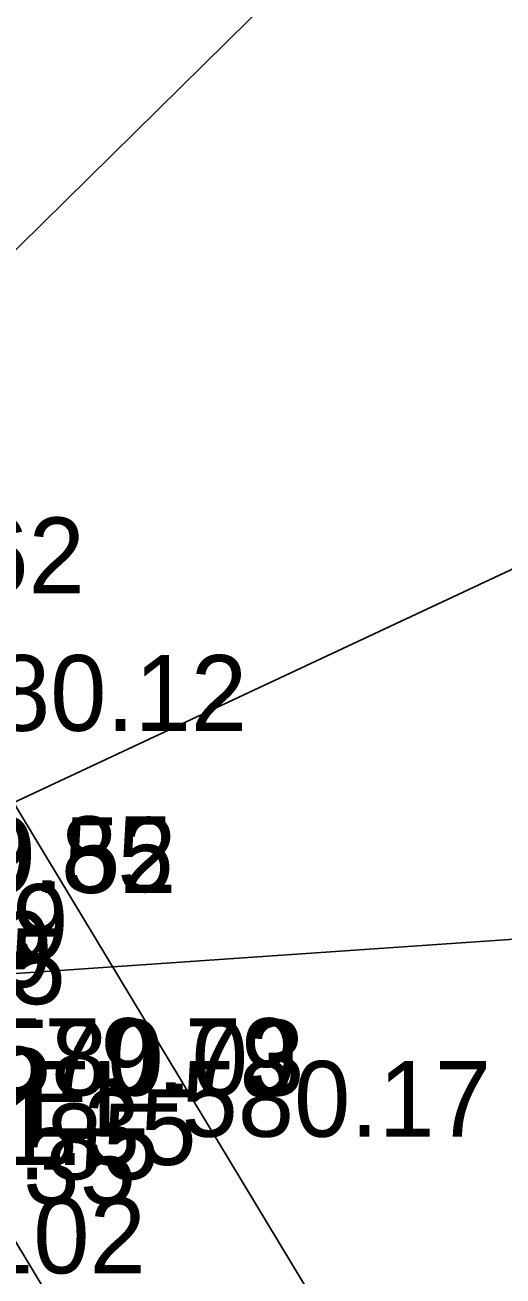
# Model space of a CAD drawing. Extents: x 1729869 to 1735532, y 648588 to 653771.
# Drawn here: x 1731709 to 1731734.2, y 651454.2 to 651520.3 of the extents above; entities that cross this region are included whole.
import ezdxf

# ---------------------------------------------------------------- set-up
doc = ezdxf.new("R2010")
doc.units = 0
for name, color, linetype in [('SURVEY - DRAINAGE - Area Shapes Text', 7, 'Continuous'), ('SURVEY - DRAINAGE - Storm Sewer', 7, 'Continuous'), ('SURVEY - DRAINAGE - Storm Sewer Text', 7, 'Continuous'), ('SURVEY - DTM - Breaklines - Points - Elevations', 7, 'Continuous'), ('SURVEY - DTM - Breaklines - Points - Numbers', 7, 'Continuous'), ('SURVEY - NON-TRANSPORTATION - Features', 7, 'Continuous'), ('SURVEY - NON-TRANSPORTATION - Features - Points - Elevations', 7, 'Continuous'), ('SURVEY - PROPERTY - ROW Lines', 7, 'Continuous')]:
    doc.layers.add(name, color=color, linetype=linetype)

msp = doc.modelspace()

# ---------------------------------------------------------------- linework, layer by layer
at = {"layer": 'SURVEY - DRAINAGE - Area Shapes Text'}
msp.add_line((1731882.052, 651679.427), (1731669.716, 651470.194), dxfattribs=at)
at = {"layer": 'SURVEY - DRAINAGE - Storm Sewer'}
msp.add_line((1731688.169, 651469.747), (1731736.421, 651492.32), dxfattribs=at)
at = {"layer": 'SURVEY - DRAINAGE - Storm Sewer Text'}
msp.add_lwpolyline([(1731686.743, 651468.674), (1731759.382, 651473.677), (1731790.368, 651426.739)], dxfattribs=at)
at = {"layer": 'SURVEY - NON-TRANSPORTATION - Features'}
msp.add_lwpolyline([(1731794.161, 651313.522), (1731781.305, 651334.978), (1731768.35, 651356.37), (1731755.374, 651377.749), (1731742.559, 651399.232), (1731729.695, 651420.682), (1731716.817, 651442.124), (1731703.914, 651463.55), (1731691.023, 651484.984), (1731678.113, 651506.405), (1731665.144, 651527.788), (1731652.209, 651549.195), (1731639.346, 651570.646), (1731622.506, 651598.643), (1731609.559, 651620.041), (1731596.626, 651641.447), (1731583.632, 651662.815), (1731569.228, 651686.906), (1731556.232, 651708.397), (1731542.125, 651732.02), (1731531.425, 651758.134)], dxfattribs=at)
at = {"layer": 'SURVEY - PROPERTY - ROW Lines'}
msp.add_line((1731636.115, 651598.792), (1731760.631, 651392.64), dxfattribs=at)

# ---------------------------------------------------------------- texts
at = {"layer": 'SURVEY - DTM - Breaklines - Points - Elevations'}
for s, p in [('EL-579.62', (1731687.444, 651490.251)), ('EL-580.12', (1731696.023, 651482.984)), ('EL-579.85', (1731692.137, 651474.467)), ('EL-579.85', (1731692.137, 651474.467)), ('EL-581.09', (1731686.582, 651470.895)), ('EL-580.03', (1731699.045, 651463.726)), ('EL-580.17', (1731708.914, 651461.55)), ('EL-581.35', (1731693.347, 651460.061)), ('EL-581.35', (1731690.143, 651458.001)), ('EL-581.35', (1731690.143, 651458.001))]:
    msp.add_text(s, height=4, dxfattribs=at).set_placement(p)
at = {"layer": 'SURVEY - DTM - Breaklines - Points - Numbers'}
for s, p in [('S15025', (1731692.674, 651468.55)), ('S15102', (1731696.909, 651454.336))]:
    msp.add_text(s, height=4, dxfattribs=at).set_placement(p)
at = {"layer": 'SURVEY - NON-TRANSPORTATION - Features - Points - Elevations'}
for s, p in [('EL-579.52', (1731692.29, 651474.422)), ('EL-579.59', (1731685.728, 651469.447)), ('EL-579.79', (1731698.684, 651463.808)), ('EL-579.85', (1731691.355, 651459.3))]:
    msp.add_text(s, height=4, dxfattribs=at).set_placement(p)

doc.saveas('drawing.dxf')
